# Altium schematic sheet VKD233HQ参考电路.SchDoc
size A4
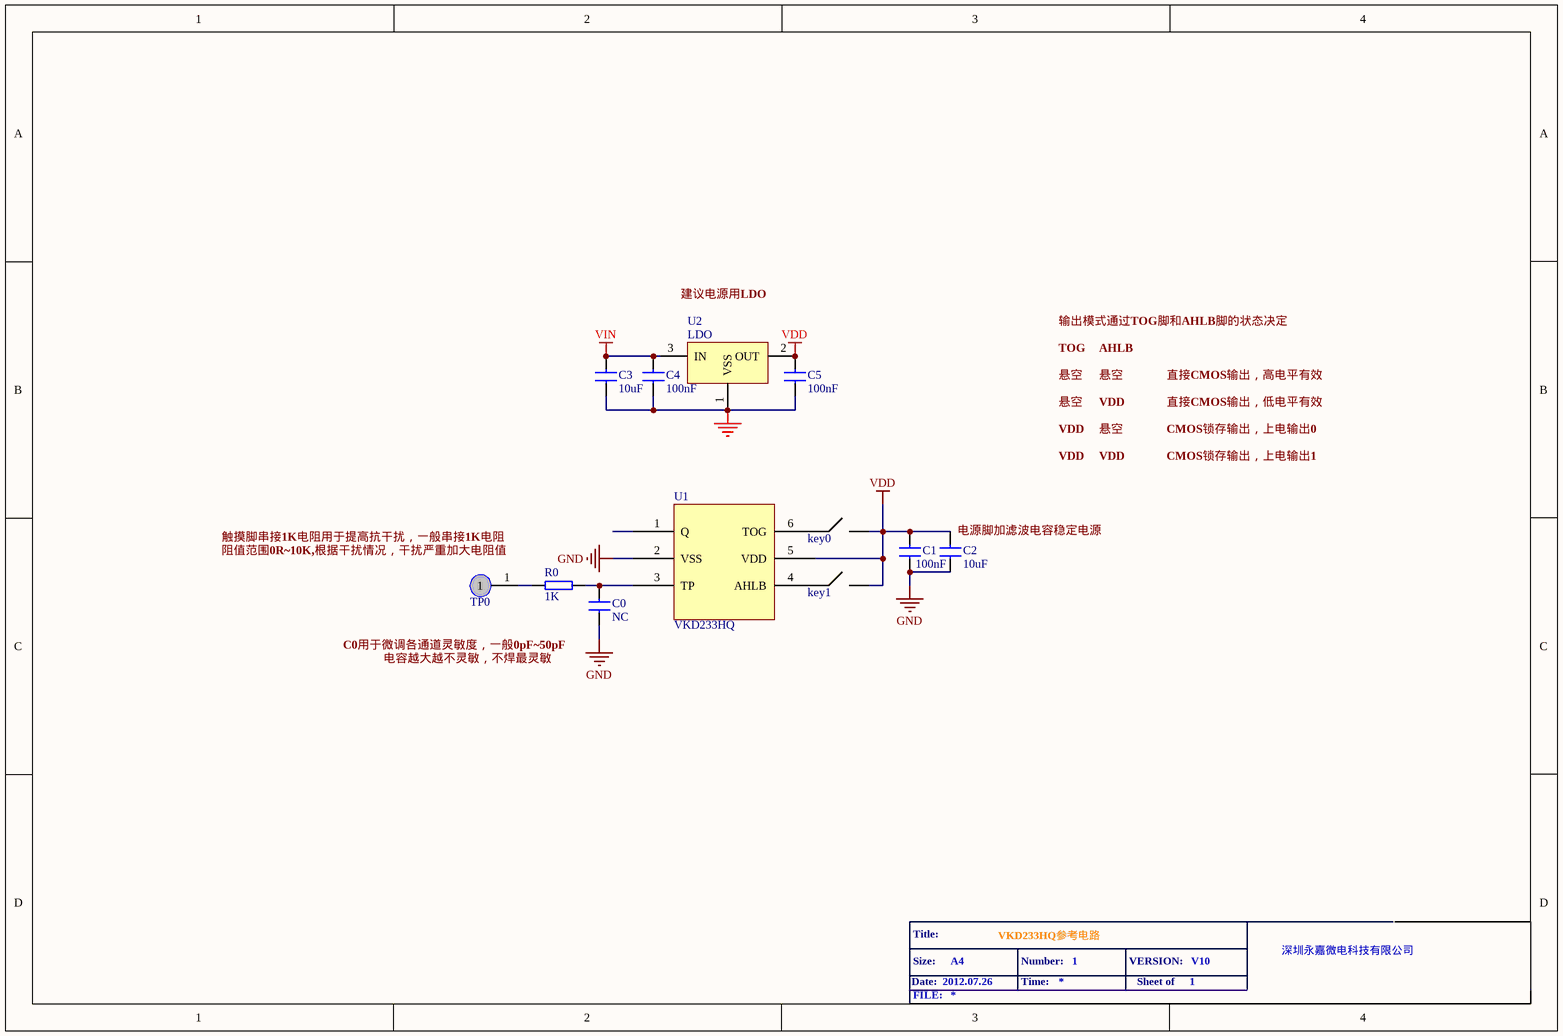
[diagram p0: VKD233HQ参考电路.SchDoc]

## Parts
C0  value NC  [0603-C]  (hidden comment: 10uF)
C1  100nF  [0603-C]
C2  10uF  [0603-C]
C3  10uF  [0805-C]
C4  100nF  [0805-C]
C5  100nF  [0805-C]
key0  单刀单掷开关  (value not drawn)
key1  单刀单掷开关  (value not drawn)
R0  1K  [0603-R]
TP0  TPAD  [TP-PAD0]  (value not drawn)
U1  VKD233HQ
U2  LDO  [SOT-23]

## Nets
GND: C0.1 C1.2 C2.2 C3.2 C4.2 C5.2 U1.2(VSS) U2.1(VSS)
VDD: C1.1 C2.1 C5.1 U1.5(VDD) U2.2(OUT)
VIN: C3.1 C4.1 U2.3(IN)
NetC0_2: C0.2 R0.1 U1.3(TP)
NetR0_2: R0.2 TP0.1

Not connected (* = marked no-connect by the designer): U1 1(Q) 4(AHLB) 6(TOG)

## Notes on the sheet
- 建议电源用LDO
- TOG
- 悬空
- 输出模式通过TOG脚和AHLB脚的状态决定
- AHLB
- 直接CMOS输出，高电平有效
- VDD
- 直接CMOS输出，低电平有效
- CMOS锁存输出，上电输出0
- CMOS锁存输出，上电输出1
- 触摸脚串接1K电阻用于提高抗干扰，一般串接1K电阻
- 阻值范围0R
  0K,根据干扰情况，干扰严重加大电阻值
- (near C2) 电源脚加滤波电容稳定电源
- C0用于微调各通道灵敏度，一般0pF~50pF
- 电容越大越不灵敏，不焊最灵敏
- Date:
- Title:
- Size:
- 2012.07.26
- A4
- VKD233HQ参考电路
- Number:
- Time:
- 1
- VERSION:
- Sheet of
- V10
- 深圳永嘉微电科技有限公司
- FILE:

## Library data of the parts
C0-C5 = CAP: Capacitor
R0 = RES: Resistor
TP0 = TPAD: TESTING
U1 = VKD233HQ SOT23-6
U2 = V6206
